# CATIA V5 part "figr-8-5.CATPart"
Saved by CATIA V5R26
Part number: Part1
Bounding box of the stored display mesh (mm): x 4.549 to 89.781, y -52.238 to 26.36, z 54 to 147.773
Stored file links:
  D:\_Deepak\CATIA\CATIA V5-6R2016_Deepak\Resources\Part files\Partfiles\c08_catia_v5_6r2016_prt\figr-8-5.CATPart
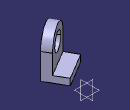
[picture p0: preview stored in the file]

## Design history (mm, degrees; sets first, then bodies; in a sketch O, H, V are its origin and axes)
Body1 (main body)
  Sketch1 on yz-plane, origin (0, 0, 0), H (0, 1, 0), V (0, 0, 1)
    point P1 (-104.4861, 0)
    line L1 (-104.4861, 0) -> (-104.4861, 44.267)
    arc A1 centre (-69.7903, 44.267) radius 34.6958 from (-104.4861, 44.267) to (-35.0946, 44.267) cw
    line L2 (-35.0946, 44.267) -> (-35.0946, 0)
    point P5 (-35.0946, 0)
    line L3 (-35.0946, 0) -> (-104.4861, 0)
    circle A2 centre (-69.7903, 44.267) radius 19.5413
    coincidence: P1 H, P5 H
    vertical: L1 V
    tangency: A1 L1, L2 A1
    horizontal: L3 H
  Pad1: profile Sketch1, direction (1, 0, 0), length 20
  Sketch2 on face of Pad1, origin (0, 0, 0), H (0, -1, 0), V (0, 0, 1)
    point P1 (35.0946, 0)
    line L1 (35.0946, 0) -> (104.4861, 0)
    line L2 (104.4861, 0) -> (104.4861, -15)
    line L3 (104.4861, -15) -> (35.0946, -15)
    line L4 (35.0946, -15) -> (35.0946, 0)
    reference projected line E1 (35.0946, 0) -> (35.0946, 44.267) from edge [face of Pad1 | face of Pad1]
    reference projected line E2 (104.4861, 44.267) -> (104.4861, 0) from edge [face of Pad1 | face of Pad1]
    distance L3 L1 = 15
    coincidence: P1 H, L4 E1, L2 E2
    horizontal: L1 H, L3 H
    vertical: L2 V, L4 V
  Pad2: profile Sketch2, direction (1, 0, 0), length 50
  Translate1: ToTransfor Pad2, Direction xy-plane, Length 69
  Rotate1: ToTransfor Translate1, Axis edge, Angle 121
